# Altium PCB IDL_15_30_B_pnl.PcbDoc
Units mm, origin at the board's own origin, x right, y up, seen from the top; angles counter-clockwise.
Board outline 119 x 62 mm, 4 copper layers (Top Layer - SIG1, Layer 2 - GND1, Layer 3 - SIG2, Bottom Layer - SIG3), stack 0.741 mm thick; 0 components, 0 nets, 0 pads, 0 vias.
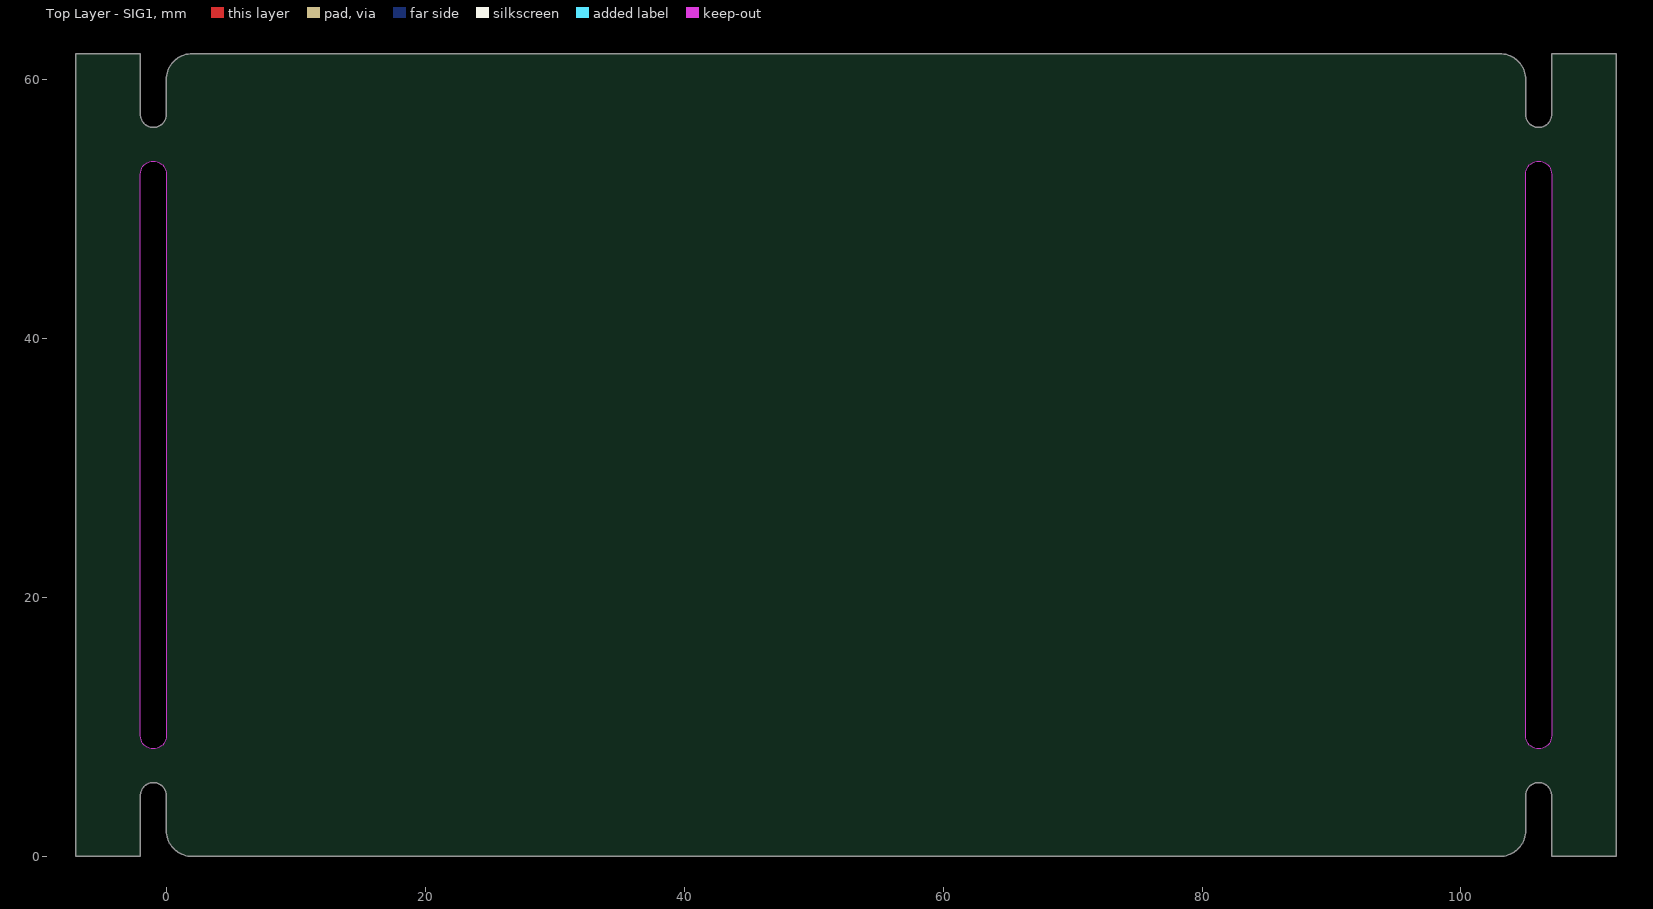
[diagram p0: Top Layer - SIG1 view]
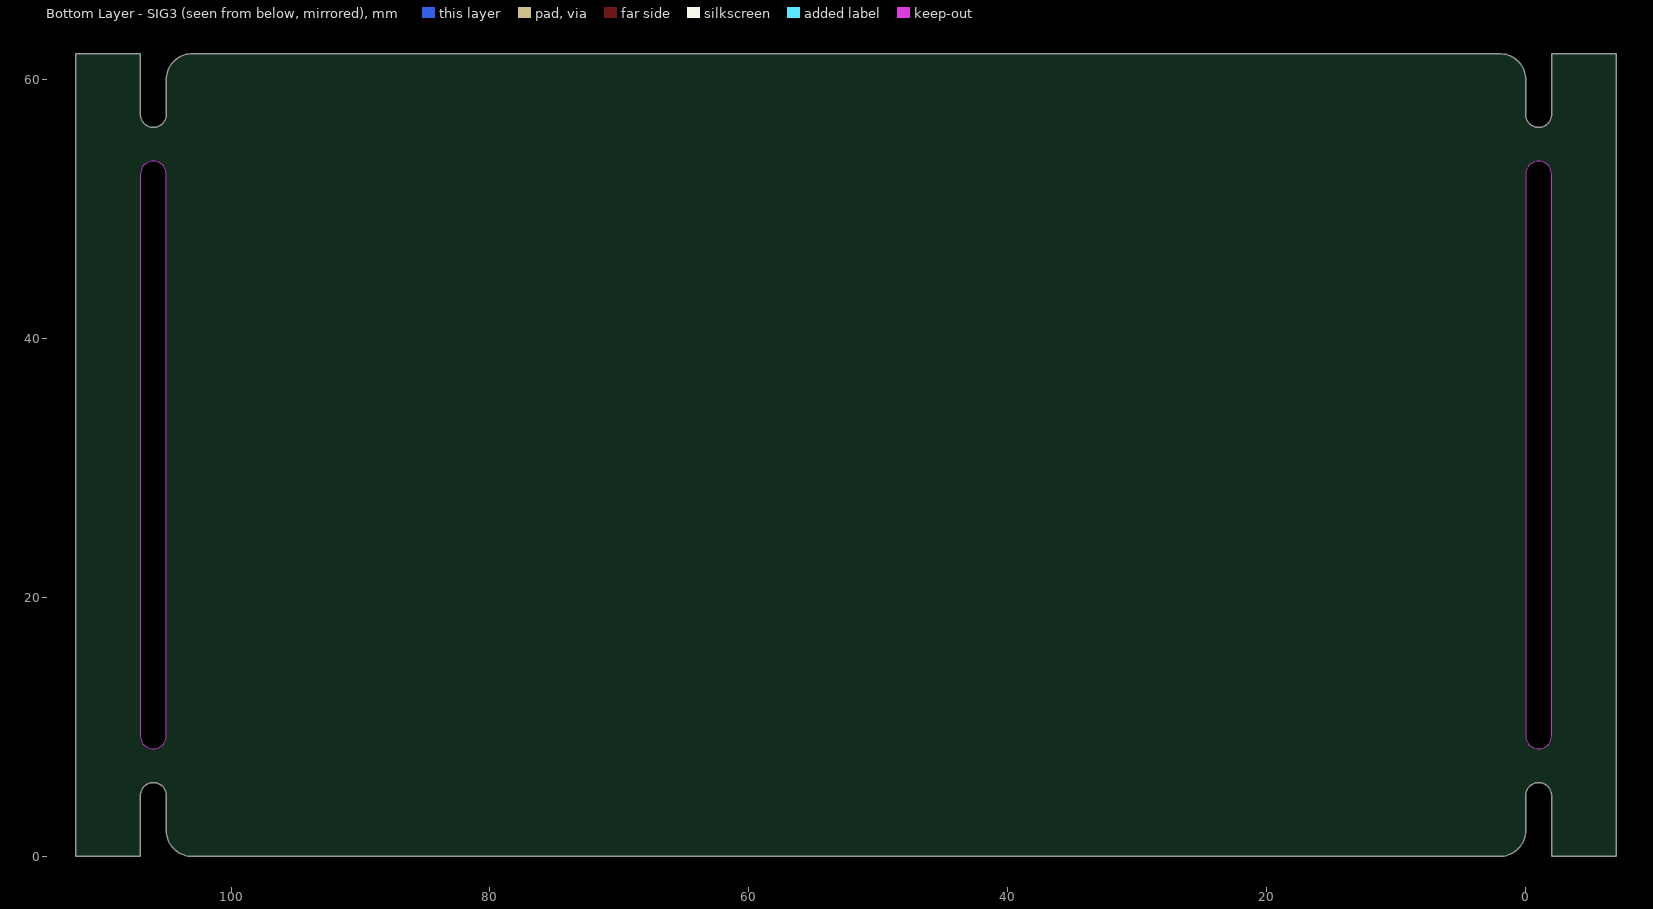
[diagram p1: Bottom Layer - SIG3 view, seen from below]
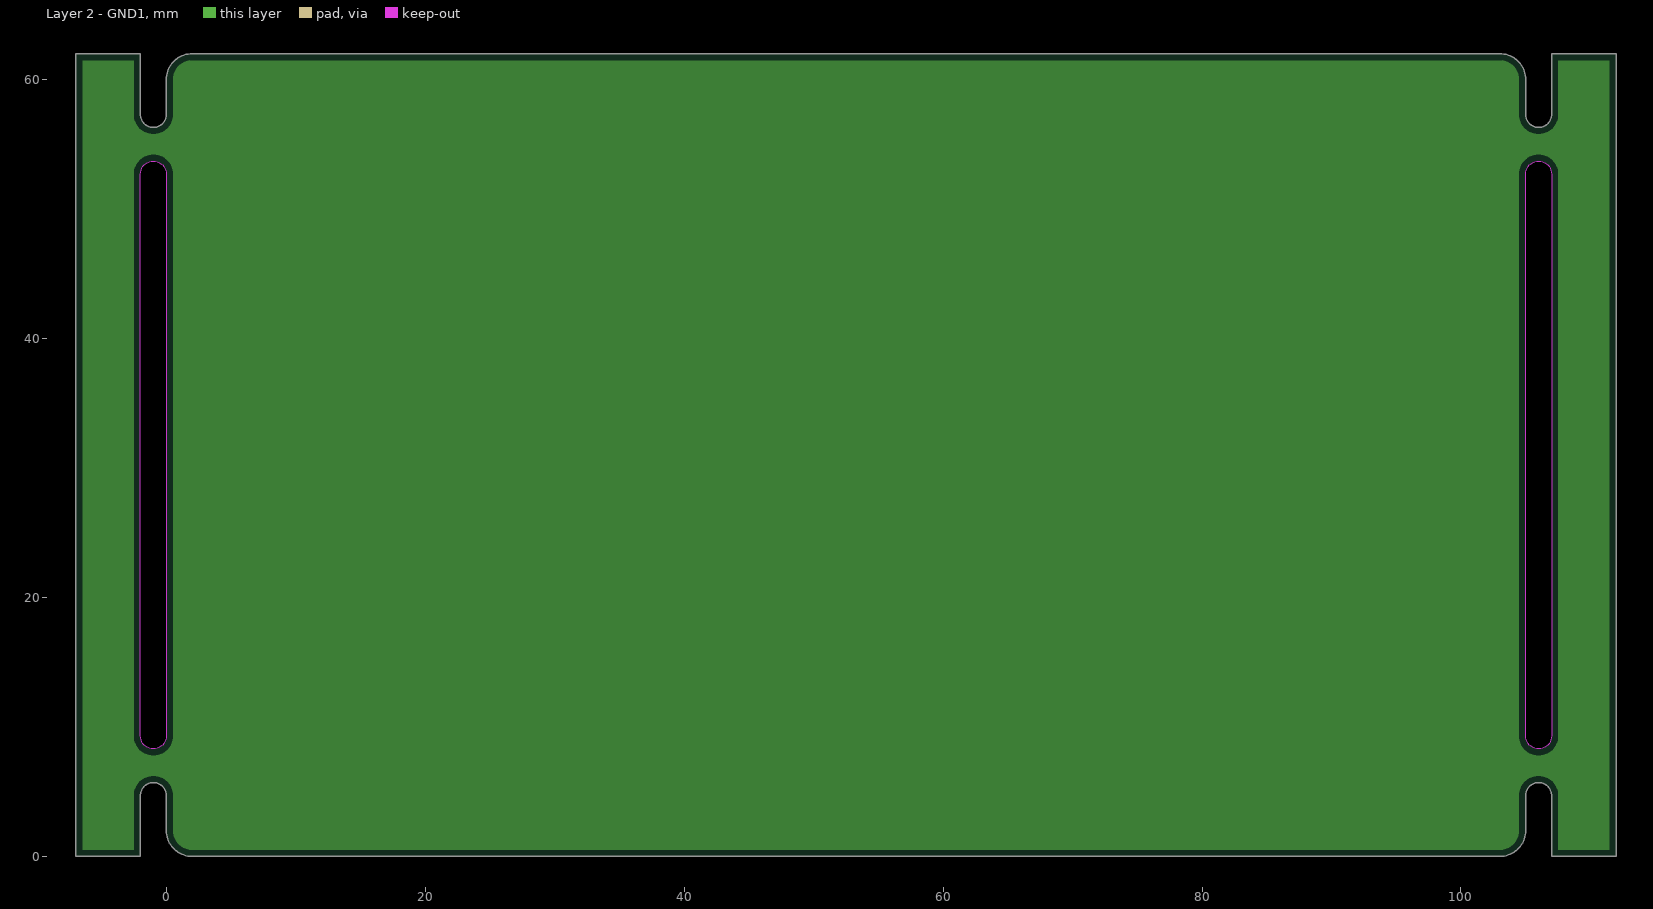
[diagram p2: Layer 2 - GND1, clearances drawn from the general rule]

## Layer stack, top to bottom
Top Solder: solder mask 0.0102, Solder Resist, Dk 3.5
Top Layer - SIG1: signal copper 0.035
Dielectric 1: core 0.254, FR-4, Dk 4.2
Layer 2 - GND1: plane copper 0.018
Dielectric 3: prepreg 0.127, FR-4, Dk 4.2
Layer 3 - SIG2: signal copper 0.018
Dielectric 6: core 0.254, FR-4, Dk 4.2
Bottom Layer - SIG3: signal copper 0.035
Bottom Solder: solder mask 0.0102, Solder Resist, Dk 3.5

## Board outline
-7,0 -2,0 -2,4.7 cw(c-1,4.7) -1,5.7 cw(c-1,4.7) 0,4.7 0,2 ccw(c2,2) 2,0 103,0 ccw(c103,2) 105,2 105,4.7 cw(c106,4.7) 106,5.7 cw(c106,4.7) 107,4.7 107,0 112,0 112,62 107,62 107,57.3 cw(c106,57.3) 106,56.3 cw(c106,57.3) 105,57.3 105,60 ccw(c103,60) 103,62 2,62 ccw(c2,60) 0,60 0,57.3 cw(c-1,57.3) -1,56.3 cw(c-1,57.3) -2,57.3 -2,62 -7,62
cut-out: 105,52.7 cw(c106,52.7) 106,53.7 cw(c106,52.7) 107,52.7 107,9.3 cw(c106,9.3) 106,8.3 cw(c106,9.3) 105,9.3 105,9.7
cut-out: -2,52.7 cw(c-1,52.7) -1,53.7 cw(c-1,52.7) 0,52.7 0,9.3 cw(c-1,9.3) -1,8.3 cw(c-1,9.3) -2,9.3 -2,9.7

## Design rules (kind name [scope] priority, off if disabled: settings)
Clearance Clearance_KeepOut [Iskeepout] p1: gap=0.508
Clearance [All] p2: gap=0.178
HoleSize [All] p1: absolutevalues=TRUE maxlimit=3.3 minlimit=0.3 maxpercent=80.000 minpercent=20.000
MinimumSolderMaskSliver [All] p1: minsoldermaskwidth=0.127
PlaneClearance [All] p1: clearance=0.254
PlaneConnect PlaneConnect_vIA [ISvIA] p1: planeconnectstyle=Direct reliefexpansion=0.508 reliefentries=4 reliefconductorwidth=0.254 reliefairgap=0.254
PlaneConnect [All] p2: planeconnectstyle=Relief reliefexpansion=0.305 reliefentries=4 reliefconductorwidth=0.254 reliefairgap=0.203
PolygonConnect PolygonConnect_Via [IsVia or HasFootprint('ChipFET1206-8') or HasFootprint('MAXB2MPCBV') or HasFootprint('MAXB5MPCBV') or HasFootprint('MAXB6MPCBV')] p1: connectstyle=Direct reliefconductorwidth=0.254 reliefentries=4 polygonreliefangle="90 Angle" airgapwidth=0.254
PolygonConnect PolygonConnect_Main [All] p2: connectstyle=Relief reliefconductorwidth=0.254 reliefentries=4 polygonreliefangle="90 Angle" airgapwidth=0.254
RoutingVias [All] p1: holewidth=0.3 width=0.65 viastyle="Through Hole" minholewidth=0.3 minwidth=0.65 maxholewidth=1 maxwidth=1.5
SilkToSilkClearance [All] p1: silktosilkclearance=0.127
SilkToSolderMaskClearance SilkscreenOverComponentPads [IsPad] p1: minsilkscreentomaskgap=0.127 clearancetoexposedcopper=TRUE
SolderMaskExpansion [All] p1: expansion=0.051
Width Width_Logo [HasFootprint('ITECH_LOGO')] p1: maxlimit=0.254 minlimit=0.025 preferedwidth=0.051
Width [All] p2: maxlimit=3.81 minlimit=0.152 preferedwidth=0.203 minimp=50.000000 maximp=50.000000 favimp=50.000000
24 further rules are at their usual default settings.

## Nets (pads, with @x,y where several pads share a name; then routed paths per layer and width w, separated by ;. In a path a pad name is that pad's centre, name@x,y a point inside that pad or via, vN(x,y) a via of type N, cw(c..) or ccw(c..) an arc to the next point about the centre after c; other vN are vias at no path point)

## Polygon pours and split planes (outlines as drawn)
no net on Layer 2 - GND1 (split plane): 386 vertices, not listed, extent -6.49,0.51 111.49,61.49

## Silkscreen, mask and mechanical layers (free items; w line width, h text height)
Board Outline:
  lines w0.1: -2,9.3 ccw(c-1,9.3) -1,8.3 ccw(c-1,9.3) 0,9.3 0,52.7 ccw(c-1,52.7) -1,53.7 ccw(c-1,52.7) -2,52.7 -2,9.3 ; -2,9.3 -2,9.3 ; 107,9.3 cw(c106,9.3) 106,8.3 cw(c106,9.3) 105,9.3 105,52.7 cw(c106,52.7) 106,53.7 cw(c106,52.7) 107,52.7 107,9.3 ; 107,9.3 107,9.3 ; -7,0 -2,0 -2,4.7 cw(c-1,4.7) -1,5.7 cw(c-1,4.7) 0,4.7 0,2 ccw(c2,2) 2,0 103,0 ccw(c103,2) 105,2 105,4.7 cw(c106,4.7) 106,5.7 cw(c106,4.7) 107,4.7 107,0 112,0 112,62 107,62 107,57.3 cw(c106,57.3) 106,56.3 cw(c106,57.3) 105,57.3 105,60 ccw(c103,60) 103,62 2,62 ccw(c2,60) 0,60 0,57.3 cw(c-1,57.3) -1,56.3 cw(c-1,57.3) -2,57.3 -2,62 -7,62 -7,0
Panel_Fid:
  circle w0.67: c3.809,9.147 r0.3
  circle w0.67: c96.139,58.42 r0.3
  circle w0.67: c3.809,9.135 r0.3
Panel_StCTop:
  lines w0.1: 4.856,8.138 20.803,-16.764 ; 89.967,-17.831 112.202,-4.162 123.659,43.859 96.959,57.859
  text "Engraved on bottom side of top paste stencil (GTP)" at 15.392,-19.634 h1.5
  text "Stencil appertures are NOT reduced!" at 22.43,-37.18 h2
  text "View from top side!" at 22.53,-40.98 h2
  text ".IDLnum" at 289.282,-162.762 h4.06
  text "STENCIL" at 263.375,-164.7 h2.54
  text ".ProjectName2" at 289.282,-167.334 h4.06
Panel_StCBot:
  text "Stencil appertures are NOT reduced!" at 22.43,-37.18 h2
  text "View from top side!" at 22.53,-40.98 h2
  text ".IDLnum" at 289.282,-162.762 h4.06
  text "STENCIL" at 263.375,-164.7 h2.54
  text ".ProjectName2" at 289.282,-167.334 h4.06
Panel_Comm:
  text "Milled with 2.0mm mill" at 22.5,-31.69 h2.54
  text ".IDLnum" at 289.282,-162.762 h4.06
  text "PANEL" at 263.375,-164.7 h2.54
  text ".ProjectName2" at 289.282,-167.334 h4.06
Panel_Sheet Top:
  lines w0.099: -70.255,-131.181 -67.715,-131.181 ; -70.255,-82.583 -67.715,-82.583 ; -70.255,-33.984 -67.715,-33.984 ; -70.255,14.615 -67.715,14.615 ; -70.255,63.213 -67.715,63.213 ; -20.09,-179.78 -20.09,-177.24 ; -20.09,109.272 -20.09,111.812 ; 30.075,-179.78 30.075,-177.24 ; 30.075,109.272 30.075,111.812 ; 80.24,-179.78 80.24,-177.24 ; 80.24,109.272 80.24,111.812 ; 130.405,-179.78 130.405,-177.24 ; 130.405,109.272 130.405,111.812 ; 180.57,-179.78 180.57,-177.24 ; 180.57,109.272 180.57,111.812 ; 230.735,-179.78 230.735,-177.24 ; 230.735,109.272 230.735,111.812 ; 280.9,-179.78 280.9,-177.24 ; 280.9,109.272 280.9,111.812 ; 328.525,-131.181 331.065,-131.181 ; 328.525,-82.583 331.065,-82.583 ; 328.525,-33.984 331.065,-33.984 ; 328.525,14.615 331.065,14.615 ; 328.525,63.213 331.065,63.213 ; -70.255,-179.778 331.063,-179.778 331.063,111.812 -70.255,111.812 -70.255,-179.778 ; -67.708,-177.245 328.516,-177.245 328.516,109.279 -67.708,109.279 -67.708,-177.245
  lines w0.1: 158.599,-177.245 158.599,-159.206 328.516,-159.206 ; 158.599,-168.331 328.525,-168.331 ; 158.599,-165.302 281.027,-165.302 ; 158.599,-162.254 281.027,-162.254 ; 196.826,-168.331 196.826,-159.206 ; 222.226,-168.331 222.226,-159.206 ; 262.612,-168.331 262.612,-159.206 ; 281.027,-177.245 281.027,-159.206 ; 281.027,-163.778 328.516,-163.778
  text "1" at -45.685,109.792 h1.52
  text "2" at 4.48,109.792 h1.52
  text "3" at 54.645,109.792 h1.52
  text "4" at 104.81,109.792 h1.52
  text "5" at 154.975,109.792 h1.52
  text "6" at 205.14,109.792 h1.52
  text "7" at 255.305,109.792 h1.52
  text "8" at 305.47,109.792 h1.52
  text "A" at -69.626,85.481 h1.52
  text "A" at 329.154,85.481 h1.52
  text "B" at -69.626,36.882 h1.52
  text "B" at 329.154,36.882 h1.52
  text "C" at -69.754,-11.717 h1.52
  text "C" at 329.026,-11.717 h1.52
  text "D" at -69.754,-60.315 h1.52
  text "D" at 329.026,-60.315 h1.52
  text "E" at -69.626,-108.914 h1.52
  text "E" at 329.154,-108.914 h1.52
  text "F" at -69.626,-157.513 h1.52
  text "F" at 329.154,-157.513 h1.52
  text "Designer:" at 159.234,-161.492 h2.54
  text ".Designer" at 173.585,-161.619 h2.54
  text "Version:" at 197.461,-161.619 h2.54
  text ".Version" at 211.685,-161.619 h2.54
  text "File:" at 222.861,-161.619 h2.54
  text ".Pcb_File_Name_No_Path" at 227.941,-161.619 h2.54
  text "Sheet  1 of  1" at 263.374,-161.619 h2.54
  text "Code:" at 281.662,-162.762 h2.54
  text "Drawn By:" at 159.234,-164.54 h2.54
  text ".Drawn_By" at 173.585,-164.54 h2.54
  text "Modif. Date:" at 197.461,-164.667 h2.54
  text "(Date)" at 210.288,-164.667 h2.54
  text "Variant:" at 222.861,-164.667 h2.54
  text ".VariantName" at 232.132,-164.667 h2.54
  text "ID:" at 281.789,-167.334 h2.54
  text "Approved By:" at 159.234,-167.588 h2.54
  text ".Approved_By" at 173.585,-167.588 h2.54
  text "Print Date:" at 197.461,-167.715 h2.54
  text ".Print_Date" at 210.288,-167.715 h2.54
  text "Signature:" at 222.861,-167.715 h2.54
  text "Size:  A3 H" at 263.374,-167.715 h2.54
  text "Title:" at 159.234,-170.89 h2.54
  text "University of Hawaii at Manoa" at 281.825,-171.1 h2.54
  text "High Energy Physics Group" at 281.825,-173.6 h2.54
  text ".Printout_Name" at 164.949,-174.446 h4.06
  text "Instrumentation Development Laboratory" at 281.825,-176.2 h2.54
  text "1" at -45.685,-179.26 h1.52
  text "2" at 4.48,-179.26 h1.52
  text "3" at 54.645,-179.26 h1.52
  text "4" at 104.81,-179.26 h1.52
  text "5" at 154.975,-179.26 h1.52
  text "6" at 205.14,-179.26 h1.52
  text "7" at 255.305,-179.26 h1.52
  text "8" at 305.47,-179.26 h1.52

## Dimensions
-7,62 to -7,0 on Mech 16
-7,62 to 112,62 on Mech 16

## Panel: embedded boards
"IDL_15_30_B.PcbDoc" at 0.021,0.021, 1 rows x 1 columns, spacing 63.5 x 38.1, rotation 0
